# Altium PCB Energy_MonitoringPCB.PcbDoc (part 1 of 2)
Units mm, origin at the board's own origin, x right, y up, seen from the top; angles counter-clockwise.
Board outline 101.22 x 43.37 mm, 4 copper layers (Top Layer, Int1 (GND), Int2 (PWR), Bottom Layer), stack 1.527 mm thick; 86 components, 79 nets, 384 pads, 136 vias.
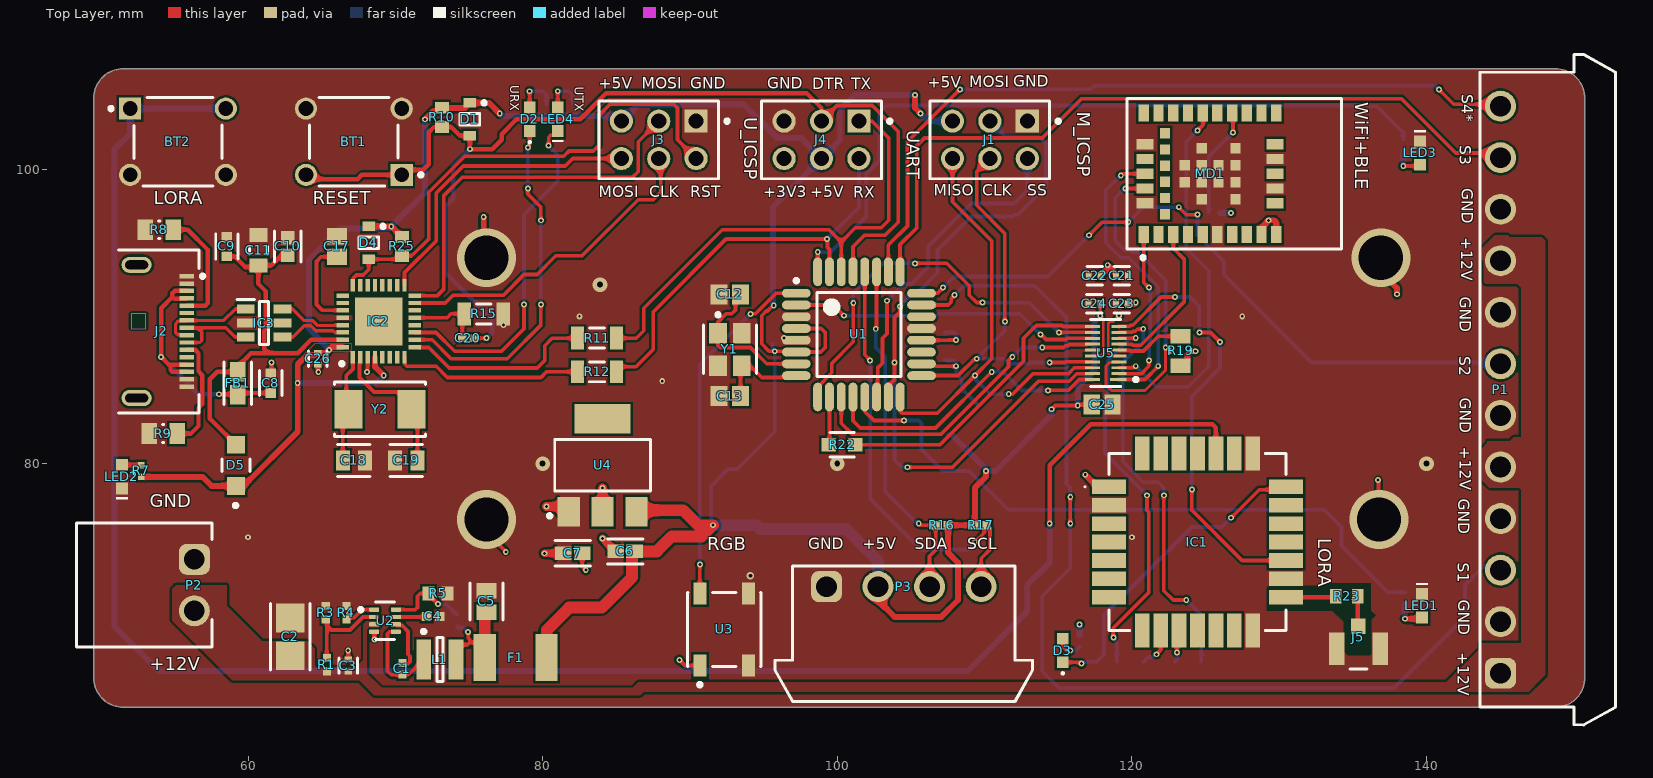
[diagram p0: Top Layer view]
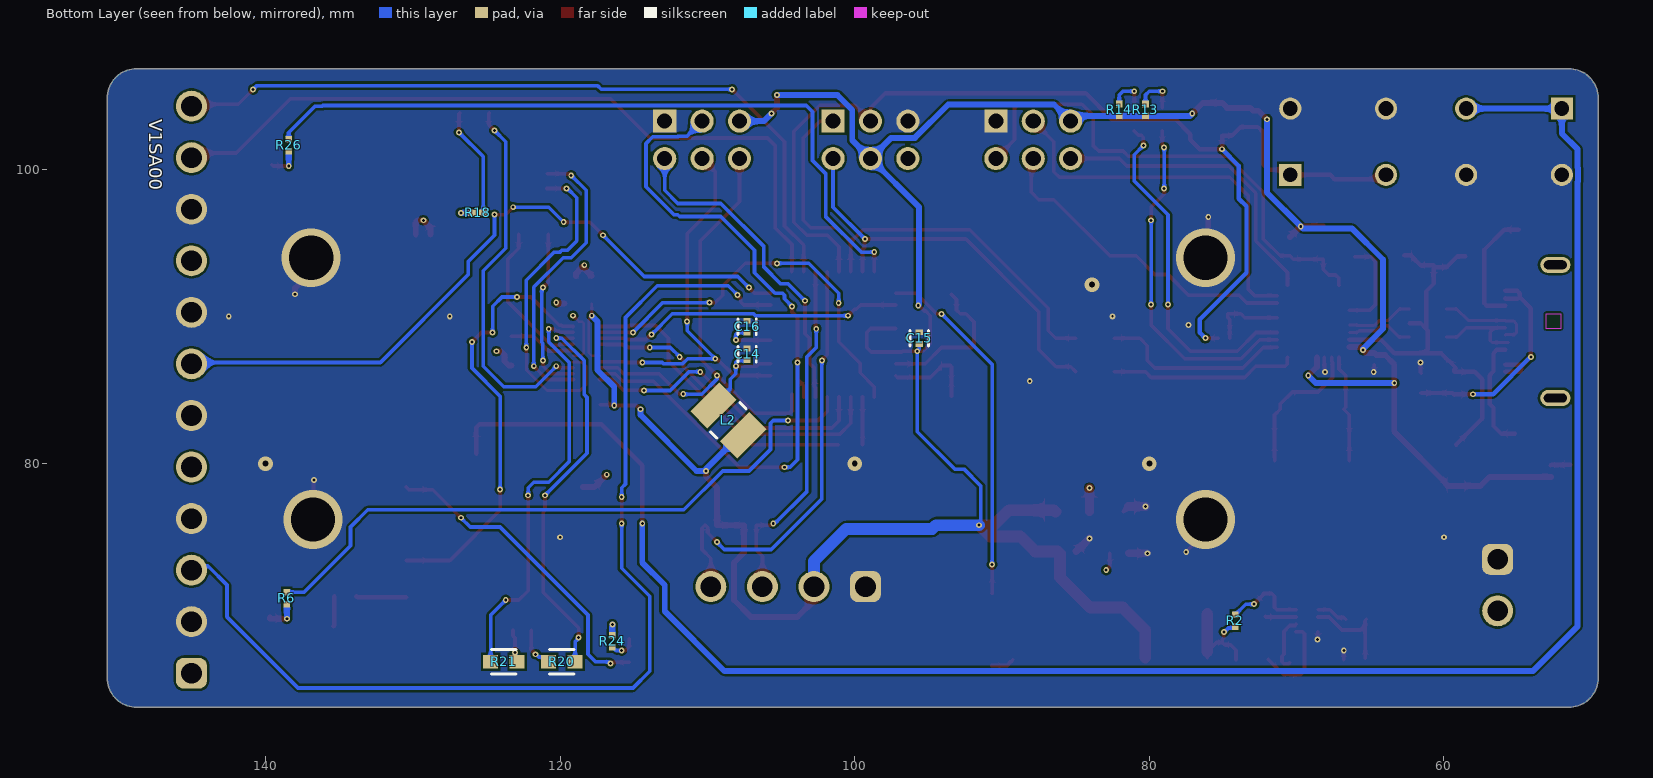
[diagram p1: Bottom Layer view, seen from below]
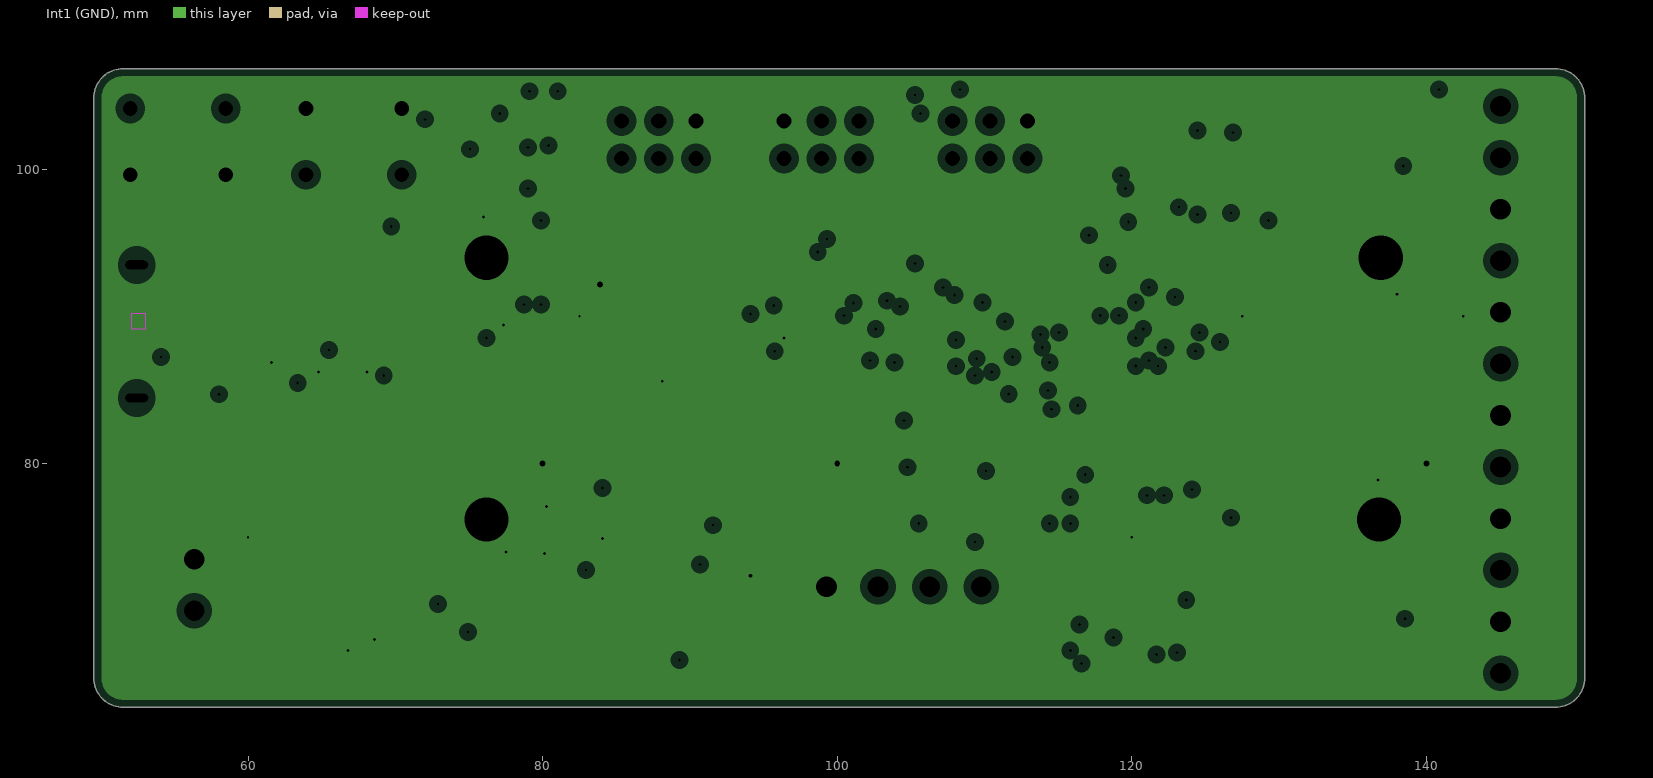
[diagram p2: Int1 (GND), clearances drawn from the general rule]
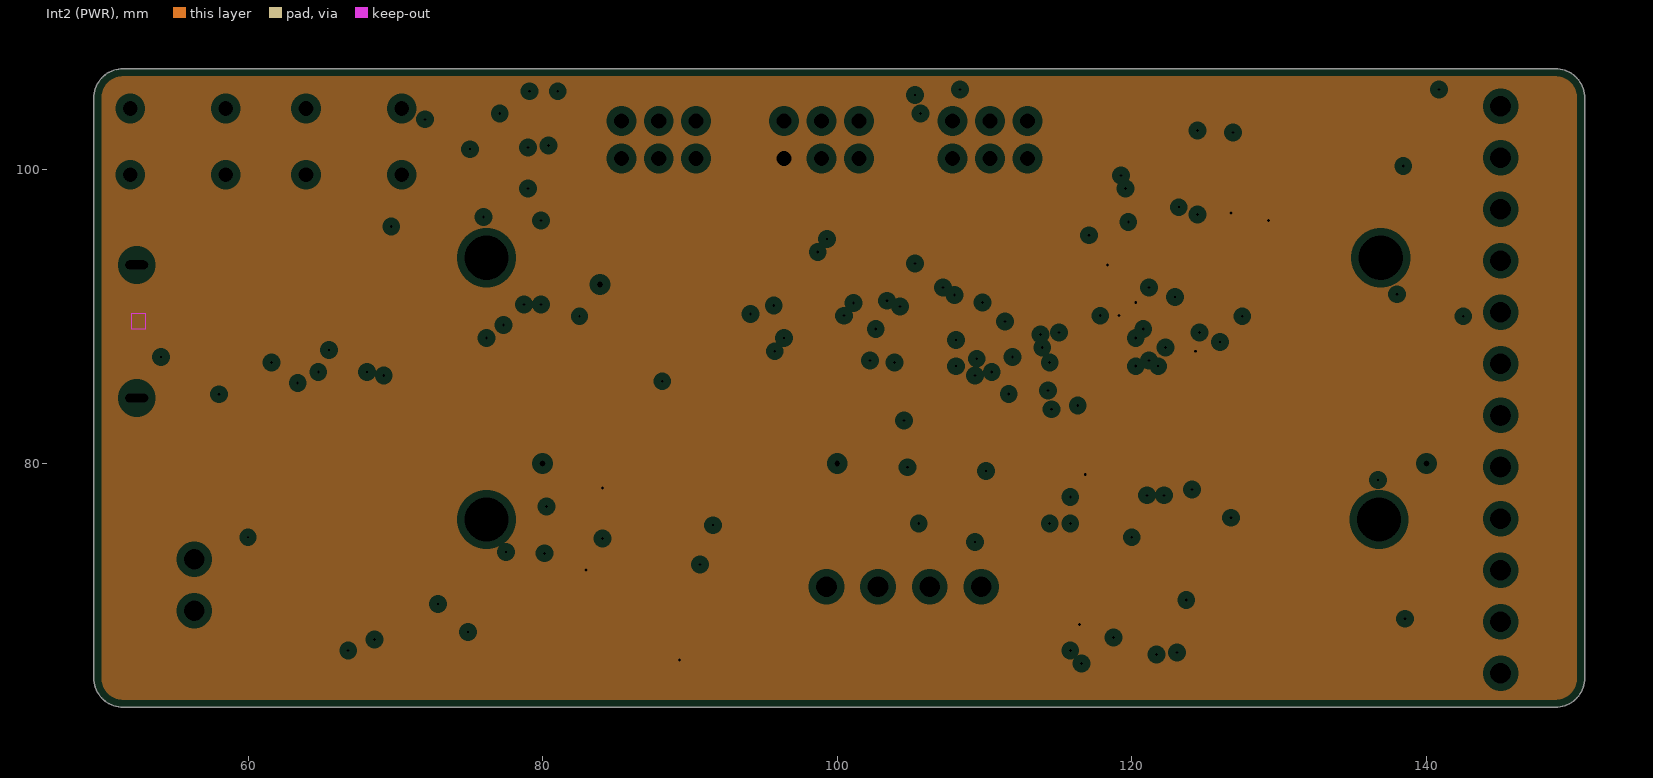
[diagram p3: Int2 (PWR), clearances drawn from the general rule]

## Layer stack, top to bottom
Top Solder: solder mask 0.0254, SM-001, Dk 4
Top Layer: signal copper 0.0175
Dielectric 1: prepreg 0.196, PP-017, Dk 4.56
Int1 (GND): plane copper 0.035, net GND
Dielectric 3: core 1.03, Core-039, Dk 4.6
Int2 (PWR): plane copper 0.035, net +3V3
Dielectric 5: prepreg 0.196, PP-017, Dk 4.56
Bottom Layer: signal copper 0.0175
Bottom Solder: solder mask 0.0254, SM-001, Dk 4

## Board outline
49.53,65.453 49.53,104.818 cw(c51.53,104.818) 51.53,106.818 148.749,106.818 cw(c148.749,104.818) 150.749,104.818 150.749,65.453 cw(c148.749,65.453) 148.749,63.453 51.53,63.453 cw(c51.53,65.453)

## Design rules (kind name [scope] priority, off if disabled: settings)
Clearance [All] p1: gap=0.15 ignorepadtopadclearanceinfootprint=TRUE except(0.1: Arc-Arc Arc-Track Track-Track)
DiffPairsRouting [InDifferentialPairClass('All Differential Pairs')] p1: maxlimit=0.127 minlimit=0.127 mostfreqgap=0.127 toplayer_minwidth=0.221 toplayer_maxwidth=0.221 toplayer_prefwidth=0.221 bottomlayer_minwidth=0.221 bottomlayer_maxwidth=0.221 bottomlayer_prefwidth=0.221 impedanceprofiledriven=TRUE impedanceprofileid={AF306077-7E99-402A-B5C2-EF889BC7BB75} impedanceprofilevalue=90.000000 maxuncoupledlength=12.7
HoleSize [All] p1: absolutevalues=TRUE maxlimit=6 minlimit=0.025 maxpercent=80.000 minpercent=20.000
HoleToHoleClearance [All] p1: gap=0.15 allowstackedmicrovias=TRUE
MinimumSolderMaskSliver [All] p1: minsoldermaskwidth=0
PlaneClearance [All] p1: clearance=0.508
PlaneConnect [All] p1: planeconnectstyle=Relief reliefexpansion=0.508 reliefentries=4 reliefconductorwidth=0.254 reliefairgap=0.254
PolygonConnect [All] p1: connectstyle=Direct reliefconductorwidth=0.254 reliefentries=4 polygonreliefangle="90 Angle" airgapwidth=0.254
RoutingVias [All] p1: holewidth=0.711 width=1.27 viastyle="Through Hole" minholewidth=0.711 minwidth=1.27 maxholewidth=0.711 maxwidth=1.27
SilkToSilkClearance [All] p1: silktosilkclearance=0
SilkToSolderMaskClearance [IsPad] p1: minsilkscreentomaskgap=0 clearancetoexposedcopper=TRUE
SolderMaskExpansion [All] p1: expansion=0.102 istentingtop=FALSE
UnRoutedNet [All] p1: checkbadconnections=TRUE
UnpouredPolygon [All] p1: allowunpoured=TRUE allowshelved=TRUE
Width [InNet('RF_OUT')] p1: maxlimit=0.331 minlimit=0.331 preferedwidth=0.331 impedanceprofiledriven=TRUE impedanceprofileid={EE7A40C8-8AAE-49D9-A8E2-67DEA738F106} impedanceprofilevalue=50.000000 minimp=50.000000 maximp=50.000000 favimp=50.000000
20 further rules are at their usual default settings.

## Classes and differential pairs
differential pair class DIF_USB: USBIN_D USBMCU_D
component class MCU+PWR+USB+SPORT: BT1 C1 C2 C3 C4 C5 C6 C7 C8 C9 C10 C11 C12 C13 C14 C15 C16 C17 C18 C19 C20 C26 D1 D2 D4 D5 F1 FB1 IC2 IC3 J1 J2 J3 J4 L1 L2 LED1 LED2 LED3 LED4 P1 P2 P3 R1 R2 R3 R4 R5 R6 R7 R8 R9 R10 R11 R12 R13 R14 R15 R16 R17 R22 R25 R26 U1 U2 U3 U4 Y1 Y2
component class Bluetooth+WiFi+LoRa: BT2 C21 C22 C23 C24 C25 D3 IC1 J5 MD1 R18 R19 R20 R21 R23 R24 U5
differential pair USBMCU_D: +USBMCU_D_P -USBMCU_D_N
differential pair USBIN_D: +USBIN_D_P -USBIN_D_N

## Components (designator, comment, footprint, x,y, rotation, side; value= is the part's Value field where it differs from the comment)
BT1 "B3F-1000" OMRON-B3F-1000-4_V 67.183,101.854 r180 top
BT2 "B3F-1000" OMRON-B3F-1000-4_V 55.245,101.854 r0 top
C1 "100nf/0402" CAPC1005X55X25LL05T10 70.485,66.083 r270 top
C2 "10UF/1206" FP-C3216-160-0_2-IPC_A 62.865,68.239 r90 top
C3 "100nf/0402" FP-GRM15-MFG 66.802,66.294 r270 top value=0.10μF
C4 "33nf" CAPC1005X55X25NL05T10 72.576,69.63 r180 top
C5 "22uf/0805" FP-GRM21B-0_2-e0_2_0_7-IPC_C 76.2,70.646 r90 top
C6 "10uf/6.3V/10%" FP-C1608-080-0_1-IPC_B 85.598,74.041 r0 top
C7 "10uf/6.3V/10%" FP-C1608-080-0_1-IPC_B 82.042,73.914 r0 top
C8 "2u2" FP-GRM188-0_1-e0_2_0_5-MFG 61.542,85.471 r90 top
C9 "2u2" FP-GRM188-0_1-e0_2_0_5-MFG 58.557,94.742 r90 top
C10 "0603/22uf/10v" FP-GRM188-0_2-IPC_C 62.685,94.742 r90 top
C11 "100nF/0603" FP-CGA3E-0_3-0_1-IPC_A 60.706,94.488 r90 top
C12 "12pf" CAPC2013X94X50LL20T25 92.71,91.486 r0 top
C13 "12pf" CAPC2013X94X50LL20T25 92.71,84.582 r0 top
C14 "100nf/0402" FP-GRM15-MFG 107.315,87.427 r270 bottom value=0.10μF
C15 "100nf/0402" FP-GRM15-MFG 95.631,88.519 r270 bottom value=0.10μF
C16 "100nf/0402" FP-GRM15-MFG 107.315,89.3 r270 bottom value=0.10μF
C17 "1UF/0805" CAPC2013X140X50LL20T25 66.04,94.742 r90 top
C18 "18pf" FP-C0805C-DN-MFG 67.183,80.214 r0 top value="18 pF"
C19 "18pf" FP-C0805C-DN-MFG 70.739,80.214 r180 top value="18 pF"
C20 "100nf/0402" CAPC1005X55X25LL05T10 74.93,88.516 r0 top
C21 "100nf/0402" FP-GRM15-MFG 119.329,92.752 r180 top value=0.10μF
C22 "100nf/0402" FP-GRM15-MFG 117.475,92.752 r0 top value=0.10μF
C23 "100nf/0402" FP-GRM15-MFG 119.318,90.864 r0 top value=0.10μF
C24 "100nf/0402" FP-GRM15-MFG 117.464,90.864 r0 top value=0.10μF
C25 "1uf/0805" CAPC2013X140X50LL20T25 117.983,84.005 r180 top
C26 "100nf/0402" FP-GRM15-MFG 64.742,87.122 r90 top value=0.10μF
D1 "BAT54HT1G/30V/2A" ONSC-SOD-323-2-477-02_V 75.057,103.378 r270 top
D2 "150060AS75020" WL-SMCW_0603_150060xx75020 79.121,103.378 r90 top
D3 "150060AS75020" WL-SMCW_0603_150060xx75020 115.316,67.31 r90 top
D4 "BAT54HT1G/30V/2A" ONSC-SOD-323-2-477-02_V 68.199,94.996 r270 top
D5 "PMEG6020AELRX" FP-SOD123W-MFG 59.182,79.883 r90 top
F1 "MF-MSMF075-2/750mA/13.2V" BOUR-MF-MSMF050-2_V 78.173,66.836 r0 top
FB1 "120R" FP-BLM18-0_15-t0_8-IPC_A 59.309,85.457 r90 top
IC1 "LoRa-E5" LoRaE5 124.46,74.676 r0 top
IC2 "ATMEGA16U2" QFN50P500X500X100-33N-D 68.871,89.658 r90 top
IC3 "USBLC6-2SC6" SOT95P280X145-6N 61.087,89.54 r0 top
J1 "M20-9980346" FP-M20-9980346-MFG 110.366,101.981 r180 top
J2 "213083-0005" FP-2130830005-MFG 52.289,88.975 r270 top
J3 "M20-9980346" FP-M20-9980346-MFG 87.884,101.981 r180 top
J4 "M20-9980346" FP-M20-9980346-MFG 98.933,101.981 r180 top
J5 "U.FL-R-SMT-1(10)" FP-U_FL-R-SMT-1_10-MFG 135.382,67.437 r0 top
L1 "3.3uh/1414" BOUR-SRN3015-2_V 73.025,66.7 r0 top
L2 "10uH/1310" FP-CB3225-IPC_A 108.585,82.939 r225 bottom
LED1 "GREEN" WL-SMCW_0603_150060xx75000 139.7,70.358 r270 top
LED2 "GREEN" WL-SMCW_0603_150060xx75000 51.435,79.121 r90 top
LED3 "GREEN" WL-SMCW_0603_150060xx75000 139.573,101.092 r270 top
LED4 "GREEN" WL-SMCW_0603_150060xx75000 81.026,103.378 r90 top
MD1 "NINA-W102-00B-00" FP-NINA-W102-00B-00-MFG 126.959,99.681 r90 top
P1 "691305140012" 691305140012 148.234,85.021 r90 top
P2 "691322110002" 691322110002 52.959,71.755 r270 top
P3 "691305140004" 691305140004 104.521,68.453 r0 top
R1 "511k" RESC1005X40X25NL05T05 65.348,66.352 r270 top
R2 "52.3 k" RESC1005X40X25LL05T05 74.168,69.342 r270 bottom
R3 "88.7k" RESC1005X40X25NL05T05 65.278,69.884 r270 top
R4 "10.7k" RESC1005X40X25NL05T05 66.675,69.884 r270 top
R5 "10k" RESC1609X50X30NL8T20 72.898,71.184 r180 top
R6 "220R/0402/5%" RESC1005X40X25LL05T05 138.557,70.866 r270 bottom
R7 "220R/0402/5%" RESC1005X40X25LL05T05 52.739,79.502 r90 top
R8 "5.1k" RESC0805(2012)_N 53.975,95.885 r0 top value="5110.00 Ohm"
R9 "5.1k" RESC0805(2012)_N 54.229,82.042 r0 top value="5110.00 Ohm"
R10 "10K/75V/1%" RESC1609X50X30NL8T20 73.152,103.505 r270 top
R11 "1K" RESC3216X70X50LL05T20 83.693,88.519 r180 top
R12 "1K" RESC3216X70X50LL05T20 83.693,86.233 r180 top
R13 "220R/0402/5%" RESC1005X40X25LL05T05 80.264,104.013 r90 bottom
R14 "220R/0402/5%" RESC1005X40X25LL05T05 82.042,104.013 r90 bottom
R15 "1K" RESC3216X70X50LL05T20 76.001,90.17 r0 top
R16 "2k2/0402" RESC1005X40X25NL5T10 107.105,75.819 r180 top
R17 "2k2/0402" RESC1005X40X25NL5T10 109.728,75.819 r0 top
R18 "220k/0201" RESC0603X26X15ML03T05 125.603,97.028 r180 bottom
R19 "100k/0805" FP-RN732A-MFG 123.306,87.653 r270 top value=100KΩ
R20 "22R/0605" FP-CPF0603-MFG 119.888,66.548 r0 bottom value=22Ω
R21 "22R/0605" FP-CPF0603-MFG 123.825,66.548 r180 bottom value=22Ω
R22 "22R/0605" FP-CPF0603-MFG 100.33,81.28 r0 top value=22Ω
R23 "0R/0603" RESC1608X55X25ML10T15 134.589,70.993 r0 top
R24 "100R/0402" RESC1005X40X25LL05T05 116.459,67.945 r90 bottom
R25 "10K/75V/1%" RESC1609X50X30NL8T20 70.443,94.742 r270 top
R26 "220R/0402/5%" RESC1005X40X25LL05T05 138.43,101.619 r270 bottom
U1 "ATmega328P-AU" 32A_M 101.473,88.773 r0 top
U2 "TPS62932DRLR" FP-DRL0008A-MFG 69.304,69.338 r0 top
U3 "1655" ADA-RGB-1655_V 92.329,68.741 r90 top
U4 "NCP1117ST33T3G" ONSC-SOT-223-4-318H-01_A_V 84.074,79.883 r90 top
U5 "TXB0108DQSR" FP-DQS0020A-MFG 118.226,87.51 r180 top
Y1 "16MHZ-12-2Z-T3" FP-ABM8AIG-MFG 92.71,87.757 r270 top
Y2 "16MHZ" FP-ABM7-MFG 68.961,83.693 r0 top

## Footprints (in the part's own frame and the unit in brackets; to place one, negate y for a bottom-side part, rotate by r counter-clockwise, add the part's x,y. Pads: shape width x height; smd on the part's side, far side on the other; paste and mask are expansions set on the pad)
32A_M [mm] "Thin QFP, 32-Leads, Body 7x7mm, Pitch 0.8mm, IPC Low Density"
  oval 1.95x0.6 smd: 1(-4.25,2.8) 2(-4.25,2) 3(-4.25,1.2) 4(-4.25,0.4) 5(-4.25,-0.4) 6(-4.25,-1.2) 7(-4.25,-2) 8(-4.25,-2.8) 17(4.25,-2.8) 18(4.25,-2) 19(4.25,-1.2) 20(4.25,-0.4) 21(4.25,0.4) 22(4.25,1.2) 23(4.25,2) 24(4.25,2.8)
  oval 0.6x1.95 smd: 9(-2.8,-4.25) 10(-2,-4.25) 11(-1.2,-4.25) 12(-0.4,-4.25) 13(0.4,-4.25) 14(1.2,-4.25) 15(2,-4.25) 16(2.8,-4.25) 25(2.8,4.25) 26(2,4.25) 27(1.2,4.25) 28(0.4,4.25) 29(-0.4,4.25) 30(-1.2,4.25) 31(-2,4.25) 32(-2.8,4.25)
  silkscreen extent -4.37,-2.85 2.85,3.77, body extent -3.5,-3.5 3.5,3.5, height 1.2
691305140004 [mm] "Horizontal PCB Header with Plastic Latch, pitch 3.5mm, 04p"
  rrect50% 2.1x2.1 hole 1.4: 1(-5.25,3.2)
  round 2.1 hole 1.4: 2(-1.75,3.2) 3(1.75,3.2) 4(5.25,3.2)
  silkscreen extent -8.75,-4.6 8.75,4.6, body extent -8.75,-4.6 8.75,4.6, height 7.25
691305140012 [mm] "Horizontal PCB Header with Plastic Latch, pitch 3.5mm, 12p"
  rrect50% 2.1x2.1 hole 1.4: 1(-19.25,3.2)
  round 2.1 hole 1.4: 2(-15.75,3.2) 3(-12.25,3.2) 4(-8.75,3.2) 5(-5.25,3.2) 6(-1.75,3.2) 7(1.75,3.2) 8(5.25,3.2) 9(8.75,3.2) 10(12.25,3.2) 11(15.75,3.2) 12(19.25,3.2)
  silkscreen extent -22.75,-4.6 22.75,4.6, body extent -22.75,-4.6 22.75,4.6, height 7.25
691322110002 [mm] "Horizontal PCB Header, pitch 3.5mm, 02p"
  rrect50% 2.1x2.1 hole 1.4: 1(-1.75,3.4)
  round 2.1 hole 1.4: 2(1.75,3.4)
  silkscreen extent -4.2,-4.6 4.2,4.6, body extent -4.2,-4.6 4.2,4.6, height 7.3
ADA-RGB-1655_V [mm] "SMD, 4-Leads, Body 5x5mm"
  rect 1.5x0.9 smd: 1(-2.45,1.65) 2(-2.45,-1.65) 3(2.45,-1.65) 4(2.45,1.65)
  silkscreen extent -3.87,-2.5 2.5,2.5, body extent -2.7,-2.5 2.7,2.5, height 1.68
BOUR-MF-MSMF050-2_V [mm] "SMD, 2-Leads, Body 4.55x3.24mm"
  rect 1.5x3.2 smd: 1(-2.1,0) 2(2.1,0)
  body extent -2.28,-1.62 2.28,1.62, height 0.85
BOUR-SRN3015-2_V [mm] "SMD, 2-Leads, Body 3x3mm, Height 1.5mm"
  rect 1x2.7 smd: 1(-1.1,0) 2(1.1,0)
  silkscreen extent -1.22,-1.5 0.2,2.02, body extent -1.5,-1.5 1.5,1.5, height 1.5
CAPC1005X55X25LL05T10 [mm] "Chip Capacitor, 2-Leads, Body 1.05x0.55mm, IPC High Density"
  rect 0.56x0.52 smd: 1(-0.39,0) 2(0.39,0)
  body extent -0.53,-0.28 0.53,0.28, height 0.55
CAPC1005X55X25NL05T10 [mm] "Chip Capacitor, 2-Leads, Body 1.00x0.50mm, IPC Medium Density"
  rect 0.66x0.62 smd: 1(-0.44,0) 2(0.44,0)
  body extent -0.53,-0.28 0.53,0.27, height 0.55
CAPC2013X94X50LL20T25 [mm] "Chip Capacitor, 2-Leads, Body 2.01x1.25mm, IPC High Density"
  rect 1.15x1.35 smd: 1(-0.725,0) 2(0.725,0)
  body extent -1.1,-0.72 1.1,0.72, height 0.94
CAPC2013X140X50LL20T25 [mm] "Chip Capacitor, 2-Leads, Body 2.00x1.25mm, IPC High Density"
  rect 1.1x1.35 smd: 1(-0.7,0) 2(0.7,0)
  body extent -1.1,-0.72 1.1,0.72, height 1.4
FP-2130830005-MFG [mm]
  rrect100% 1.1x2.05 hole 1.55 slot 0.6 at 0 deg paste-2539.97 mask+0: 3(-4.52,0.15) 4(4.52,0.15)
  rect 0.3x1 smd paste+0 mask+0: A1(-3.75,3.55) A4(-2.75,3.55) A5(-1.75,3.55) A6(-0.75,3.55) A7(0.75,3.55) A8(1.75,3.55) A9(2.75,3.55) A12(3.75,3.55) B1(3.25,3.55) B4(2.25,3.55) B5(1.25,3.55) B6(0.25,3.55) B7(-0.25,3.55) B8(-1.25,3.55) B9(-2.25,3.55) B12(-3.25,3.55)
  Keep-Out Layer region: -1.195,-0.219 -0.195,-0.219 -0.195,0.781 -1.195,0.781
  silkscreen extent -5.53,-1.07 5.53,4.75, body extent -5.33,-4.18 5.33,4.18, height 0.25
FP-ABM7-MFG [mm]
  rect 1.9x2.6 smd paste+0 mask+0: 1(-2.15,0) 2(2.15,0)
  silkscreen extent -3.1,-1.85 3.1,1.85, body extent -3.2,-1.95 3.2,1.95, height 0.25
FP-ABM8AIG-MFG [mm]
  rect 1.4x1.2 smd paste+0 mask+0: 1(-1.1,-0.8) 2(1.1,-0.8) 3(1.1,0.8) 4(-1.1,0.8)
  silkscreen extent -2.47,-1.8 1.65,1.8, body extent -1.9,-1.5 1.9,1.5, height 0.25
FP-BLM18-0_15-t0_8-IPC_A [mm]
  rect 1.306x1.058 smd paste+0 mask+0: 1(-0.776,0) 2(0.776,0)
  silkscreen extent -1.43,-0.93 1.43,0.93, body extent -1.93,-1.03 1.93,1.03, height 0.25
FP-C0805C-DN-MFG [mm]
  rect 0.95x1.35 smd paste+0 mask+0: 1(-0.75,0) 2(0.75,0)
  silkscreen extent -1.1,-1.07 1.1,1.07, body extent -1.4,-0.85 1.4,0.85, height 0.25
FP-C1608-080-0_1-IPC_B [mm]
  rect 1.131x0.912 smd paste+0 mask+0: 1(-0.641,0) 2(0.641,0)
  silkscreen extent -1.21,-0.86 1.21,0.86, body extent -1.46,-0.71 1.46,0.71, height 0.25
FP-C3216-160-0_2-IPC_A [mm]
  rect 1.954x1.906 smd paste+0 mask+0: 1(-1.276,0) 2(1.276,0)
  silkscreen extent -2.25,-1.35 2.25,1.35, body extent -2.75,-1.45 2.75,1.45, height 0.25
FP-CB3225-IPC_A [mm]
  rect 1.654x2.806 smd paste+0 mask+0: 1(-1.426,0) 2(1.426,0)
  silkscreen extent -0.3,-1.4 0.3,1.4, body extent -1.6,-1.25 1.6,1.25, height 2.7
FP-CGA3E-0_3-0_1-IPC_A [mm]
  rect 0.956x1.206 smd paste+0 mask+0: 1(-1.025,0) 2(1.025,0)
  silkscreen extent -0.25,-0.6 0.25,0.6, body extent -2,-1.1 2,1.1, height 0.25
FP-CPF0603-MFG [mm]
  rect 1x0.9 smd paste+0 mask+0: 1(-0.9,0) 2(0.9,0)
  silkscreen extent -0.82,-0.82 0.82,0.82, body extent -0.77,-0.4 0.77,0.4, height 0.55
FP-DQS0020A-MFG [mm]
  rect 1.1x0.2 smd paste-1000 mask+0: 1(-0.85,1.8)
  rect 1x0.2 smd paste-1000 mask+0: 2(-0.9,1.4) 3(-0.9,1) 4(-0.9,0.6) 5(-0.9,0.2) 6(-0.9,-0.2) 7(-0.9,-0.6) 8(-0.9,-1) 9(-0.9,-1.4) 10(-0.9,-1.8) 11(0.9,-1.8) 12(0.9,-1.4) 13(0.9,-1) 14(0.9,-0.6) 15(0.9,-0.2) 16(0.9,0.2) 17(0.9,0.6) 18(0.9,1) 19(0.9,1.4) 20(0.9,1.8)
  silkscreen extent -2.17,-2.27 1.02,2.27, body extent -1.5,-2.12 1.5,2.12, height 0.25
FP-DRL0008A-MFG [mm]
  rrect33% 0.67x0.3 smd paste+0 mask+0: 1(-0.74,0.75) 2(-0.74,0.25) 3(-0.74,-0.25) 4(-0.74,-0.75) 5(0.74,-0.75) 6(0.74,-0.25) 7(0.74,0.25) 8(0.74,0.75)
  silkscreen extent -1.77,-1.28 0.65,1.28, body extent -1.17,-1.35 1.17,1.35, height 0.25
FP-GRM15-MFG [mm]
  rect 0.4x0.5 smd paste+0 mask+0: 1(-0.4,0) 2(0.4,0)
  silkscreen extent -0.53,-0.63 0.53,0.63, body extent -0.7,-0.38 0.7,0.38, height 0.25
FP-GRM21B-0_2-e0_2_0_7-IPC_C [mm]
  rect 1.055x1.356 smd paste+0 mask+0: 1(-0.726,0) 2(0.726,0)
  silkscreen extent -1.25,-1.12 1.25,1.12, body extent -1.35,-0.82 1.35,0.82, height 0.25
FP-GRM188-0_1-e0_2_0_5-MFG [mm]
  rect 0.65x0.7 smd paste+0 mask+0: 1(-0.675,0) 2(0.675,0)
  silkscreen extent -0.85,-0.75 0.85,0.75, body extent -1.1,-0.55 1.1,0.55, height 0.25
FP-GRM188-0_2-IPC_C [mm]
  rect 0.905x0.906 smd paste+0 mask+0: 1(-0.601,0) 2(0.601,0)
  silkscreen extent -1.05,-0.9 1.05,0.9, body extent -1.15,-0.6 1.15,0.6, height 0.25
FP-M20-9980346-MFG [mm]
  rect 1.57x1.57 hole 1.02 paste-2539.97 mask+0: 1(-2.54,-1.27)
  round 1.57 hole 1.02 paste-2539.97 mask+0: 2(-2.54,1.27) 3(0,-1.27) 4(0,1.27) 5(2.54,-1.27) 6(2.54,1.27)
  silkscreen extent -4.76,-2.64 4.06,2.64, body extent -4.16,-2.74 4.16,2.74, height 0.25
FP-NINA-W102-00B-00-MFG [mm]
  rect 1.15x0.7 smd paste+0 mask+0: 1(-4.125,6.15) 2(-4.125,5.15) 3(-4.125,4.15) 4(-4.125,3.15) 5(-4.125,2.15) 6(-4.125,1.15) 7(-4.125,0.15) 8(-4.125,-0.85) 9(-4.125,-1.85) 10(-4.125,-2.85) 16(4.125,-2.85) 17(4.125,-1.85) 18(4.125,-0.85) 19(4.125,0.15) 20(4.125,1.15) 21(4.125,2.15) 22(4.125,3.15) 23(4.125,4.15) 24(4.125,5.15) 25(4.125,6.15)
  rect 0.7x1.15 smd paste+0 mask+0: 11(-2,-2.775) 12(-1,-2.775) 13(0,-2.775) 14(1,-2.775) 15(2,-2.775) 26(2,6.075) 27(1,6.075) 28(0,6.075) 29(-1,6.075) 30(-2,6.075)
  rect 0.7x0.7 smd paste+0 mask+0: 31(-2.75,4.7) 32(-1.65,4.7) 33(-0.55,4.7) 34(0.55,4.7) 35(1.65,4.7) 36(2.75,4.7) 37(-0.575,3.37) 38(0.575,3.37) 39(-1.725,2.22) 40(-0.575,2.22) 41(0.575,2.22) 42(1.725,2.22) 43(-0.575,1.07) 44(0.575,1.07) 45(-1.725,-0.08) 46(-0.575,-0.08) 47(0.575,-0.08) 48(1.725,-0.08)
  silkscreen extent -5.82,-7.27 5.1,7.27, body extent -5.2,-7.37 5.2,7.37, height 0.25
FP-RN732A-MFG [mm]
  rect 1x1.35 smd paste+0 mask+0: 1(-1,0) 2(1,0)
  silkscreen extent -0.13,-0.7 0.13,0.7, body extent -1.6,-0.8 1.6,0.8, height 0.25
FP-SOD123W-MFG [mm]
  rect 1.2x1.2 smd paste-1000 mask+0: 1(-1.4,0) 2(1.4,0)
  silkscreen extent -2.85,-0.95 0.43,0.95, body extent -2.2,-1.05 2.2,1.05, height 0.25
FP-U_FL-R-SMT-1_10-MFG [mm]
  rect 1x1.05 smd paste-1000 mask+0: 1(0,1.525)
  rect 1.05x2.2 smd paste-1000 mask+0: 2(-1.475,0) 3(1.475,0)
  silkscreen extent -0.58,-1.38 0.58,-1.38, body extent -2.1,-1.48 2.1,2.15, height 0.25
LoRaE5 [mm]
  rect 2.3x1 smd: 1(-6,3.75) 2(-6,2.5) 3(-6,1.25) 4(-6,0) 5(-6,-1.25) 6(-6,-2.5) 7(-6,-3.75) 15(6,-3.75) 16(6,-2.5) 17(6,-1.25) 18(6,0) 19(6,1.25) 20(6,2.5) 21(6,3.75)
  rect 1x2.3 smd: 8(-3.75,-6) 9(-2.5,-6) 10(-1.25,-6) 11(0,-6) 12(1.25,-6) 13(2.5,-6) 14(3.75,-6) 22(3.75,6) 23(2.5,6) 24(1.25,6) 25(0,6) 26(-1.25,6) 27(-2.5,6) 28(-3.75,6)
  silkscreen extent -7.7,-6 6,6, body extent -6,-6 6,6, height 2.6
OMRON-B3F-1000-4_V [mm] "TH, 4-Leads, Body 6x6mm"
  rect 1.5x1.5 hole 1 paste-2539.97: 1(-3.25,2.25)
  round 1.5 hole 1 paste-2539.97: 2(3.25,2.25) 4(3.25,-2.25)
  round 1.5 hole 1 paste-2539.97 mask+0.102: 3(-3.25,-2.25)
  silkscreen extent -4.68,-3 3,3, body extent -3,-3 3,3, height 4.5
ONSC-SOD-323-2-477-02_V [mm] "SOD, 2-Leads, Body 1.7x1.25mm"
  rect 0.63x0.83 smd: 1(-1.115,0) 2(1.115,0)
  silkscreen extent -1.24,-0.67 0.4,1.09, body extent -0.85,-0.63 0.85,0.63, height 1.06
ONSC-SOT-223-4-318H-01_A_V [mm] "SOT223, 4-Leads, Body 6.5x3.5mm, Pitch 2.3mm"
  rect 2x1.5 smd: 1(-3.15,2.3) 2(-3.15,0) 3(-3.15,-2.3)
  rect 2x3.8 smd: 4(3.15,0)
  silkscreen extent -3.55,-3.25 1.75,3.72, body extent -1.75,-3.25 1.75,3.25, height 1.8
QFN50P500X500X100-33N-D [mm]
  rect 0.85x0.3 smd: 1(-2.45,1.75) 2(-2.45,1.25) 3(-2.45,0.75) 4(-2.45,0.25) 5(-2.45,-0.25) 6(-2.45,-0.75) 7(-2.45,-1.25) 8(-2.45,-1.75) 17(2.45,-1.75) 18(2.45,-1.25) 19(2.45,-0.75) 20(2.45,-0.25) 21(2.45,0.25) 22(2.45,0.75) 23(2.45,1.25) 24(2.45,1.75)
  rect 0.3x0.85 smd: 9(-1.75,-2.45) 10(-1.25,-2.45) 11(-0.75,-2.45) 12(-0.25,-2.45) 13(0.25,-2.45) 14(0.75,-2.45) 15(1.25,-2.45) 16(1.75,-2.45) 25(1.75,2.45) 26(1.25,2.45) 27(0.75,2.45) 28(0.25,2.45) 29(-0.25,2.45) 30(-0.75,2.45) 31(-1.25,2.45) 32(-1.75,2.45)
  rect 3.25x3.25 smd: 33(0,0)
  silkscreen extent -3,2.37 -2.75,2.62, body extent -2.55,-2.55 2.55,2.55, height 1
RESC0603X26X15ML03T05 [mm] "Chip Resistor, 2-Leads, Body 0.60x0.30mm, IPC Low Density"
  rect 0.55x0.45 smd: 1(-0.375,0) 2(0.375,0)
  body extent -0.32,-0.16 0.32,0.17, height 0.26
RESC0805(2012)_N [mm] "Chip Resistor, Body 2.0x1.3mm, IPC Medium Density"
  rect 1.05x1.4 smd: 1(-0.95,0) 2(0.95,0)
  silkscreen extent -0.05,-0.6 0.05,0.6, body extent -1.1,-0.67 1.1,0.68, height 0.7
RESC1005X40X25LL05T05 [mm] "Chip Resistor, 2-Leads, Body 1.00x0.50mm, IPC High Density"
  rect 0.45x0.45 smd: 1(-0.4,0) 2(0.4,0)
  body extent -0.53,-0.27 0.53,0.28, height 0.4
RESC1005X40X25NL05T05 [mm] "Chip Resistor, 2-Leads, Body 1.00x0.50mm, IPC Medium Density"
  rect 0.55x0.55 smd: 1(-0.45,0) 2(0.45,0)
  body extent -0.53,-0.27 0.53,0.28, height 0.4
RESC1005X40X25NL5T10 [mm] "Chip Resistor, 2-Leads, Body 1.05x0.55mm, IPC Medium Density"
  rect 0.6x0.55 smd: 1(-0.425,0) 2(0.425,0)
  body extent -0.53,-0.28 0.53,0.28, height 0.4
RESC1608X55X25ML10T15 [mm] "Chip Resistor, 2-Leads, Body 1.60x0.80mm, IPC Low Density"
  rect 0.8x1 smd: 1(-0.75,0) 2(0.75,0)
  body extent -0.85,-0.45 0.85,0.45, height 0.55
RESC1609X50X30NL8T20 [mm] "Chip Resistor, 2-Leads, Body 1.65x0.95mm, IPC Medium Density"
  rect 0.8x0.95 smd: 1(-0.65,0) 2(0.65,0)
  body extent -0.82,-0.48 0.82,0.48, height 0.5
RESC3216X70X50LL05T20 [mm] "Chip Resistor, 2-Leads, Body 3.20x1.60mm, IPC High Density"
  rect 0.9x1.55 smd: 1(-1.325,0) 2(1.325,0)
  silkscreen extent -0.5,-0.67 0.5,0.67, body extent -1.63,-0.82 1.62,0.82, height 0.7
SOT95P280X145-6N [mm]
  rect 1.2x0.6 smd: 1(-1.25,0.95) 2(-1.25,0) 3(-1.25,-0.95) 4(1.25,-0.95) 5(1.25,0) 6(1.25,0.95)
  silkscreen extent -1.85,-1.46 0.3,1.6, body extent -1.4,-1.46 1.4,1.46, height 1.45
WL-SMCW_0603_150060xx75000 [mm] "SMD Mono-color Chip LED, body 1.6x0.8mm"
  rect 0.8x0.8 smd: 1(-0.8,0) 2(0.8,0)
  silkscreen extent -1.55,-0.4 -1.4,0.4, body extent -0.8,-0.4 0.8,0.4, height 0.7
WL-SMCW_0603_150060xx75020 [mm] "SMD Mono-color Chip LED, body 1.6x0.8mm"
  rect 0.8x0.8 smd: 1(-0.8,0) 2(0.8,0)
  silkscreen extent -1.62,-0.08 -1.48,0.07, body extent -0.8,-0.4 0.8,0.4, height 0.25

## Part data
BT1 BT2: library part CMP-1677-00002-1, "Tactile Switch, SPST-NO, 0.05 A, 5 to 24 V, -25 to 70 degC, 4-Pin THD, RoHS, Bulk", Capacitance="-45 f", Current Rating="1.5 A", Max Operating Temperature="70 degC", Min Operating Temperature="-40 degC", Package Quantity=1080, Voltage Rating="150 V"
C1 C20: library part CMP-2000-06331-1, "Chip Capacitor, 0.1 uF, +/- 10%, 10 V, -55 to 125 degC, 0402 (1005 Metric), RoHS, Tape and Reel", Capacitance=100000pF, Case Size/Dimension=0402, Dielectric=X7R, Manufacturer=Murata, Package Description="2-Pin Surface Mount Device, Body 1 x 0.5 mm", Rated Voltage=10V, Tolerance (%)=±10%
C2: library part CMP-2000-06045-2, "Multilayer Ceramic Capacitors 10uF ±10% 50V X5R SMD 1206", Capacitance=10uF, Case Code (Imperial)=1206, Case Code (Metric)=3216, Dielectric=X5R, Dielectric Material=Ceramic, Max Operating Temperature=85°C, Min Operating Temperature=-55°C, Package Quantity=1, Tolerance=10%, Voltage=50V
C3 C14 C15 C16 C21 C22 C23 C24 C26: library part CMP-2100-03641-2, "CAP CER 0.1UF 16V X7R 0402", Capacitance=0.10μF, Manufacturer=Murata, Manufacturer Part Number=GRM155R71C104KA88D, Package=GRM15, Temperature="-55°C to +125°C", Temperature Characteristic=X7R, Temperature Range High=+125°C, Temperature Range Low=-55°C, Tolerance=10%, Voltage Rating=16Vdc
C4: library part CMP-2008-04594-1, Manufacturer=Murata, Part Number=GRM155R71A333KA01D
C5: library part CMP-06035-039918-1, "Chip Multilayer Ceramic Capacitors for General Purpose, 0805, 22uF, X5R, 15%, 20%, 10V", Capacitance=22uF, Case Code (Imperial)=0805, Case Code (Metric)=2012, Dielectric=X5R, Dielectric Material=Ceramic, Max Operating Temperature=85°C, Min Operating Temperature=-55°C, Package Quantity=3000, Tolerance=20%, Voltage=10V
C6 C7: library part CMP-08246-005333-1, "Multilayer Ceramic Capacitors 10μF ±10% 6.3V X5R SMD 0603", Capacitance=10uF, Case Code (Imperial)=0603, Case Code (Metric)=1608, Dielectric=X5R, Dielectric Material=Ceramic, Max Operating Temperature=85°C, Min Operating Temperature=-55°C, Package Quantity=1, Tolerance=10%, Voltage=6.3V
C8 C9: library part CMP-2006-02836-2, "Chip Multilayer Ceramic Capacitors for General Purpose, 0603, 2.2uF, X7R, 15%, 10%, 10V", Capacitance=2.2uF, Case Code (Imperial)=0603, Case Code (Metric)=1608, Dielectric=X7R, Max Operating Temperature=125°C, Min Operating Temperature=-55°C, Package Quantity=1, Tolerance=10%, Voltage=10V
C10: library part CMP-2000-06337-3, "Chip Multilayer Ceramic Capacitors for General Purpose, 0603, 22uF, X5R, 15%, 20%, 10V", Capacitance=22uF, Case Code (Imperial)=0603, Case Code (Metric)=1608, Dielectric=X5R, Max Operating Temperature=85°C, Min Operating Temperature=-55°C, Package Quantity=4000, Tolerance=20%, Voltage Rating=10V
C11: library part CMP-2000-07546-2, "Cap Ceramic 100nF 50V X7R 10% Pad SMD 0603 +125°C Automotive T/R", Capacitance=100nF, Case Code (Imperial)=0603, Case Code (Metric)=1608, Dielectric=X7R, Max Operating Temperature=125°C, Min Operating Temperature=-55°C, Package Quantity=1, Ratings=AEC-Q200, Tolerance=10%, Voltage=50V
C12 C13: library part CMP-2007-04128-1, Manufacturer="AVX Interconnect / Elco", Part Number=08051A120JAT2A
C17 C25: library part CMP-2007-03234-1, Manufacturer=Kemet, Part Number=C0805C105K3RACTU
C18 C19: library part CMP-2007-00302-2, "CAP CER 18PF 50V C0G/NP0 0805", Capacitance="18 pF", Manufacturer=KEMET, Manufacturer Part Number=C0805C180J5GACTU, Package=C0805C-DN, Temperature="-55°C to +125°C", Temperature Characteristic=C0G, Temperature Coefficient=30ppm/°C, Temperature Range High=+125°C, Temperature Range Low=-55°C, Tolerance=0.05, Voltage Rating="50 V"
D1 D4: library part CMP-1055-00462-1, "Schottky Barrier Diode, 2-Pin SOD-323, Pb-Free, Tape and Reel", Manufacturer="On Semiconductor", PartNumber=BAT54HT1G
D2 D3: library part CMP-03913-104891423-2, "WL-SMCW SMT Mono-Color Chip LED Waterclear super f", Forward Current=60mA, Forward Voltage=2V, Max Operating Temperature=85°C, Max Reverse Voltage (DC)=5V, Min Operating Temperature=-40°C
D5: library part CMP-14398-000040-1, "DIODE SCHOTTKY 60V 2A CFP3"
F1: library part CMP-2100-03654-1, "PTC Resettable Fuse, 13.2 V, 750 mA, -40 to 85 degC, 2-Pin SMD, RoHS, Tape and Reel", Case Code (Imperial)=1812, Case Code (Metric)=4532, Current Rating=100A, Manufacturer=Bourns, Max Operating Temperature=85degC, Min Operating Temperature=-40degC, Package Description="2-Pin Surface Mount Device, Body 4.55 x 3.24 mm", Package Quantity=2000, Package Reference=MF-MSMF050-2, Power Dissipation=800mW, Resistance=450mOhm, Supply Voltage=13.2V
FB1: library part CMP-0686-00557-7, "Chip Ferrite Bead, 0603, 120Ω @ 100MHz, 0.05Ω, 25%, 2A", Case Code (Imperial)=0603, Case Code (Metric)=1608, Current Rating=2A, DC Resistance (DCR)=50mR, Frequency=100MHz, Max Operating Temperature=125°C, Min Operating Temperature=-55°C, Package Quantity=1, Tolerance=25%
IC1: "Integrated Circuit", Manufacturer_Name="Seeed Studio"
IC2: "Integrated Circuit", Manufacturer_Name=Microchip, Mouser Part Number=N/A
IC3: "Integrated Circuit", Manufacturer_Name=STMicroelectronics, Mouser Part Number=511-USBLC6-2SC6
J1 J3 J4: library part CMP-2000-06636-2, "CONN HEADER VERT 6POS 2.54MM", Current Rating=3A, Manufacturer=Harwin, Temperature="-40°C to +105°C", Temperature Range High=+105°C, Temperature Range Low=-40°C
J2: library part CMP-04767-000030-2, "CONN RCP USB2.0 TYP C 24P SMD RA", Current Rating=5A, Max Operating Temperature=85°C, Min Operating Temperature=-40°C, Voltage Rating=30V
J5: library part CMP-2000-05152-3, "CONN U.FL RCPT STR 50 OHM SMD", Dielectric Material=Polymer, Frequency=6GHz, Housing Color=Beige, Insulation Resistance=500MR, Max Operating Temperature=90°C, Min Operating Temperature=-40°C, Package Quantity=2500
L1: library part CMP-0007-00001-1, "Semi-shielded Power Inductor, 3.3 uH, +/- 20%, 1.6 A, -40 to 125 degC, 3 x 3 x 1.5 mm SMD, RoHS and Halogen Free, Tape and Reel", Inductance="3.3 uH", Inductance tolerance="+/- 20%", Manufacturer=Bourns, Operating Temperature="-40 to 125 degC", PartNumber=SRN3015-3R3M, Rated current="1.6 A", Resistance to Solder Heat="+260 degC for 10 sec."
L2: library part CMP-14484-000123-1, "SMD Inductors 10uH ±20% 0.9A 0.1729Ω 1210", Case Code (Imperial)=1210, Case Code (Metric)=3225, Current Rating=900mA, DC Resistance (DCR)=172.9mR, Inductance=10uH, Inductance tolerance=20%, Max Operating Temperature=105°C, Min Operating Temperature=-40°C, Package Quantity=1000, Resistor Type=Wirewound, Self Resonant Frequency=23MHz, Test Frequency=100kHz
LED1 LED2 LED3 LED4: library part CMP-1426-00006-6, Case Code (Imperial)=0603, Case Code (Metric)=1608, Color=Green, Forward Current=100mA, Forward Voltage=2V, Max Junction Temperature (Tj)=95°C, Max Operating Temperature=85°C, Max Reverse Voltage (DC)=5V, Min Operating Temperature=-40°C, Power Dissipation=72mW, Test Current=20mA
MD1: library part CMP-207130-000007-1, "STAND-ALONE MULTIRADIO MODULES", Manufacturer=U-Blox, Max Frequency=2.5GHz, Max Supply Voltage=3.6V, Min Supply Voltage=3V, Nominal Supply Current=30-190mA, Package=0, Receiving Current=100-140mA, Temperature="-40°C to +85°C", Temperature Range High=+85°C, Temperature Range Low=-40°C, Transmitting Current=225-320mA
P1: library part CMP-1502-01782-2
P2: library part CMP-1502-01791-3, Color=Green, Current=10A, Max Operating Temperature=105°C, Min Operating Temperature=-40°C, Voltage=300V
P3: library part CMP-1502-01777-2
R1: library part CMP-2002-00076-1, Manufacturer="Vishay Dale", Part Number=CRCW0402511KFKED
R2: library part CMP-2002-00086-1, Manufacturer="Vishay Dale", Part Number=CRCW040252K3FKED
R3: library part CMP-2002-00251-1, Manufacturer="Vishay Dale", Part Number=CRCW040288K7FKED
R4: library part CMP-1011-00626-2, Manufacturer="Vishay Dale", Part Number=CRCW040210K7FKED
R5 R10 R25: library part CMP-1666-00005-4, "Chip Resistor, 10 KOhm, +/- 1%, 100 mW, -55 to 155 degC, 0603 (1608 Metric), RoHS, Tape and Reel", Manufacturer="Vishay Semiconductor", Max Operating Temperature="155 degC", Min Operating Temperature="-55 degC", Package Quantity=5000, Voltage Rating="75 V"
R6 R7 R13 R14 R26: library part CMP-2002-00487-3, "Chip Resistor, 220 Ohm, +/- 5%, 100 mW, -55 to 155 degC, 0402 (1005 Metric), RoHS, Tape and Reel", Case Code (Imperial)=0402, Case Code (Metric)=1005, Manufacturer="Basic Passives", Max Operating Temperature="155 degC", Min Operating Temperature="-55 degC", Package Quantity=10000, PartNumber=ERJ-2GEJ221X, Power Rating="100 mW", Resistance="220 Ohm", Tolerance=5%, Voltage Rating="50 V"
R8 R9: library part CMP-1013-00591-1, "5K11 0.125W 1% 0805 (2012 Metric)  SMD", Case-EIA=0805, Case-Metric=2012, Power="0.125 W", Tolerance="1 %"
R11 R12 R15: library part CMP-2003-00017-1, Manufacturer=Panasonic, Part Number=ERJ-8ENF1001V
R16 R17: library part CMP-2002-07969-2, "Chip Resistor, 2.2 KOhm, +/- 5%, 0.063 W, -55 to 155 degC, 0402 (1005 Metric), RoHS, Tape and Reel", Case Code (Imperial)=0402, Case Code (Metric)=1005, Max Operating Temperature="155 degC", Min Operating Temperature="-55 degC", Package Quantity=10000, Power Rating="63 mW", Resistance="2.2 kohm", Tolerance=5%, Voltage Rating="50 V"
R18: library part CMP-2004-03487-1, Manufacturer=Panasonic, Part Number=ERJ1GNF2203C
R19: library part CMP-03211-002801-1, "SMD Chip Resistor, Thin Film, 100KΩ, 100 V, 0805 [2012 Metric], 100 mW, 0.1%, RN73 Series", Manufacturer="TE Connectivity", Manufacturer Part Number=RN73C2A100KBTDF, Package=RN732A, Power Rating=0.1W, Resistance=100KΩ, Temperature="-55°C to 155°C", Temperature Coefficient=10ppm/°C, Temperature Range High=155°C, Temperature Range Low=-55°C, Tolerance=0.1%, Voltage Rating=100V
R20 R21 R22: library part CMP-03211-007811-1, "RES SMD 22Ω 0.1% 1/16W 0603", Manufacturer="TE Connectivity", Manufacturer Part Number=CPF0603B22RE1, Package=CPF0603, Power Rating=0.063W, Resistance=22Ω, Temperature="-55°C to +155°C", Temperature Coefficient=25ppm/°C, Temperature Range High=+155°C, Temperature Range Low=-55°C, Tolerance=0.1%, Voltage Rating=50V
R23: library part CMP-2100-03667-1, "Chip Resistor, 0 Ohm, +/- 5%, 0.1 W, -55 to 155 degC, 0603 (1608 Metric), RoHS, Tape and Reel", Case Code (Imperial)=0603, Case Code (Metric)=1608, Manufacturer=Yageo, Max Operating Temperature=155degC, Min Operating Temperature=-55degC, Package Description="2-Pin Surface Mount Device, Body 1.6 x 0.8 mm", Package Quantity=5000, Power Rating=100mW, Resistance=0mOhm, Temperature Coefficient=200ppm/degreesC, Tolerance=5%, Voltage Rating=50V
R24: library part CMP-2002-00605-3, "Chip Resistor, 100 Ohm, +/- 1%, 100 mW, -55 to 155 degC, 0402 (1005 Metric), RoHS, Tape and Reel", Case Code (Imperial)=0402, Case Code (Metric)=1005, Manufacturer="Basic Passives", Max Operating Temperature="155 degC", Min Operating Temperature="-55 degC", Package Quantity=10000, PartNumber=ERJ-2RKF1000X, Power Rating="100 mW", Resistance="100 Ohm", Tolerance=1%, Voltage Rating="50 V"
U1: library part CMP-0095-00269-2, "8-bit AVR Microcontroller, 32KB Flash, 1KB EEPROM, 2KB SRAM, 32-pin TQFP, Industrial Grade (-40°C to 85°C)"
U2: library part CMP-04918-000714-1, "3.8-V TO 30-V INPUT, 2-A, 200-KH"
U3: library part CMP-2000-05026-1, "Intelligent Control LED Integrated Light Source, 3.5 to 5.3 V, -25 to 80 degC, 4-Pin SMD, RoHS, Tape and Reel", Color=Red,Green,Blue(RGB), Manufacturer=Adafruit-Industries-LLC, Package Description="4-Pin Surface Mount Device, Body 5 x 5 mm"
U4: library part CMP-1679-00010-1, "Low-Dropout Positive Fixed Voltage Regulator, 1 A, 3.3 V Output Voltage, 0 to 125 degC, 4-Pin SOT-223 (318H-01), Pb-Free, Tape and Reel", Case Code (Imperial)=0603, Case Code (Metric)=1608, Max Operating Temperature="155 degC", Min Operating Temperature="-55 degC", Package Quantity=5000, Power Rating="100 mW", Resistance="220 kohm", Tolerance=1%, Type (Resistor)="Thick Film", Voltage Rating="75 V"
U5: library part CMP-04899-000009-1, "IC TRNSLTR BIDIRECTIONAL 20USON", Ambient Temperature Range High=+85°C, Ambient Temperature Range Low=-40°C, Manufacturer="Texas Instruments", Max Junction Temp=+150°C, Max Supply Voltage=5.5V, Min Supply Voltage=1.2V, Nominal Supply Current=0.05-3.5uA, Package=DQS0020A, Temperature="-40°C to +85°C"
Y1: library part CMP-27762-000014-2, "Crystal 16MHz ±20ppm (Tol) ±50ppm (Stability) 12pF FUND 70Ω Automotive 4-Pin Ultra Mini-CSMD T/R", Case/Package=SMD/SMT, ESR (Equivalent Series Resistance)=70R, Frequency=16MHz, Frequency Stability=50ppm, Frequency Tolerance=20ppm, Load Capacitance=12pF, Max Operating Temperature=125°C, Min Operating Temperature=-40°C, Ratings=AEC-Q200
Y2: library part CMP-27762-000095-1, "Crystal 16MHz ±20ppm 18pF SMD-2 6mm x 3.5mm", Case/Package=CSMD, ESR (Equivalent Series Resistance)=50R, Frequency=16MHz, Frequency Stability=30ppm, Frequency Tolerance=20ppm, Load Capacitance=18pF, Max Operating Temperature=85°C, Min Operating Temperature=-40°C, Operating Frequency="16 MHz", Package Quantity=1000, Resistor Type=Ceramic

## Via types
v1: diameter 0.4, hole 0.2, Top Layer to Bottom Layer, 120 vias
v2: diameter 0.4, hole 0.16, Top Layer to Bottom Layer, 6 vias
v3: diameter 1, hole 0.4, Top Layer to Bottom Layer, 4 vias
v4: diameter 4, hole 3, Top Layer to Bottom Layer, 4 vias
v5: diameter 0.4, hole 0.2, Top Layer to Int2 (PWR), 1 vias
v6: diameter 0.508, hole 0.254, Top Layer to Int1 (GND), 1 vias

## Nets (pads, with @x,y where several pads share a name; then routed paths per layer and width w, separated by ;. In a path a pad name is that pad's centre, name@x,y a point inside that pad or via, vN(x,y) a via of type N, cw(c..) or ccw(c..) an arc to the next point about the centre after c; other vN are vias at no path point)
+3V3: C7.2 C21.2 C22.2 C23.2 IC1.1 J4.6 MD1.9 MD1.10 R18.1 R19.2 R24.2 U3.1 U4.2 U5.5 | length 18.4
  Top Layer w0.17: U5.5@119.126,87.31 119.111,87.325 118.579,87.325 118.391,87.512 118.391,89.507 118.529,89.645 118.728,89.645 v1(119.126,90.043)
  Top Layer w0.25: C7.2@82.683,73.914 82.683,73.019 v1(82.931,72.771) ; v5(89.281,66.675) 89.665,66.291 U3.1@90.679,66.291
  Top Layer w0.4: v1(116.84,79.248) 117.662,78.426 IC1.1@118.46,78.426 ; C22.2@117.875,92.752 118.364,93.241 v1(118.364,93.472) 118.929,92.907 C21.2@118.929,92.752 ; C23.2@119.718,90.864 120.201,90.864 v1(120.269,90.932) ; R19.2@123.306,86.653 123.481,86.653 123.781,86.953 123.781,87.396 124.015,87.63 v1(124.333,87.63) ; MD1.9@128.809,95.556 128.809,96.043 v1(129.286,96.52) 129.667,96.52 129.809,96.378 MD1.10@129.809,95.556
  Top Layer w0.6: U4.2@84.074,76.733 v1(84.074,78.359)
  Bottom Layer w0.4: R24.2@116.459,68.345 v1(116.459,69.088) ; R18.1@125.978,97.028 v1(126.746,97.028)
